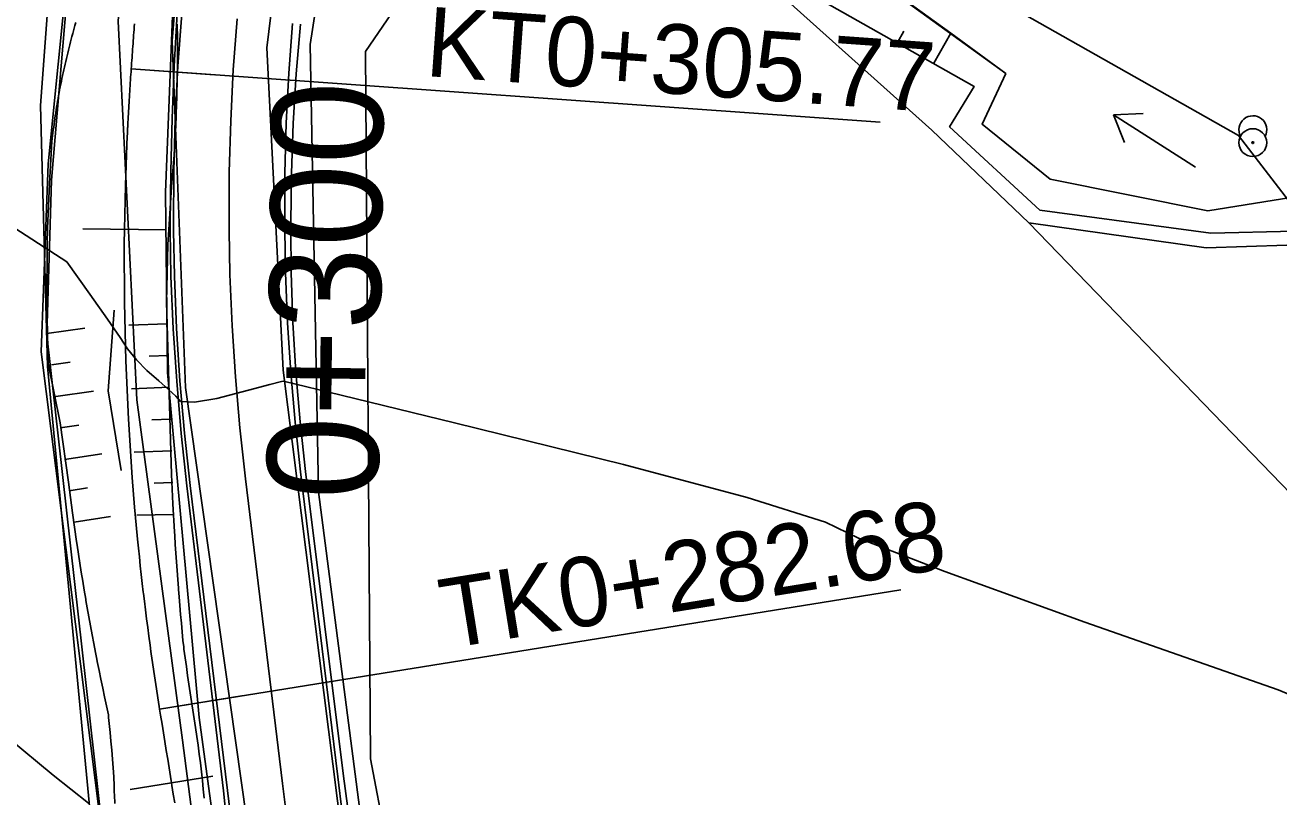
# Model space of a CAD drawing. Extents: x -574342 to -508101, y -1143544 to -1123894.
# Drawn here: x -508550.57 to -508505.49, y -1143220.32 to -1143192.58 of the extents above; entities that cross this region are included whole.
import ezdxf

# ---------------------------------------------------------------- set-up
doc = ezdxf.new("R2010")
doc.units = 0
for name, color, linetype in [('01_PARCELY_NAVRH_PC', 7, 'Continuous'), ('01_PARCELY_NAVRH_VHO', 7, 'Continuous'), ('01_PARCELY_NAVRH_ŽP', 7, 'Continuous'), ('05_VHO_V_TOK_STAV', 7, 'Continuous'), ('1000', 7, 'Continuous'), ('18', 7, 'Continuous'), ('21', 7, 'Continuous'), ('23', 7, 'Continuous'), ('30', 7, 'Continuous'), ('37', 7, 'Continuous'), ('42', 7, 'Continuous'), ('43', 7, 'Continuous'), ('55', 7, 'Continuous'), ('6', 7, 'Continuous'), ('60', 7, 'Continuous'), ('61', 7, 'Continuous'), ('62', 7, 'Continuous'), ('tab', 7, 'Continuous'), ('VRST VEDL', 7, 'Continuous')]:
    doc.layers.add(name, color=color, linetype=linetype)

msp = doc.modelspace()

# ---------------------------------------------------------------- linework, layer by layer
for p, q in [((-508549.793, -1143203.663), (-508548.424, -1143203.467)), ((-508545.467, -1143203.314), (-508546.849, -1143203.364)), ((-508546.114, -1143204.481), (-508545.428, -1143204.456)), ((-508548.95, -1143204.696), (-508549.63, -1143204.793)), ((-508549.471, -1143205.925), (-508548.117, -1143205.737)), ((-508545.385, -1143205.598), (-508546.751, -1143205.652)), ((-508546.02, -1143206.767), (-508545.338, -1143206.739)), ((-508548.639, -1143206.964), (-508549.316, -1143207.056)), ((-508549.16, -1143208.188), (-508547.81, -1143207.995)), ((-508545.292, -1143207.881), (-508546.654, -1143207.929)), ((-508545.932, -1143209.04), (-508545.258, -1143209.023)), ((-508548.325, -1143209.216), (-508548.992, -1143209.318)), ((-508548.815, -1143210.447), (-508547.506, -1143210.242)), ((-508545.233, -1143210.165), (-508546.557, -1143210.194))]:
    msp.add_line(p, q)
at = {"layer": '01_PARCELY_NAVRH_PC'}
msp.add_lwpolyline([(-508524.26, -1143263.08), (-508531.16, -1143250.06), (-508535.34, -1143238.37), (-508537.02, -1143231.11), (-508538.46, -1143221.35), (-508540.02, -1143209.35), (-508540.32, -1143193.28), (-508538.65, -1143182.46), (-508537.18, -1143176.51), (-508541.94, -1143173.53), (-508544.25, -1143181.83), (-508544.97, -1143188.3), (-508545.24, -1143191.32), (-508545.52, -1143198.58), (-508545.45, -1143205.07), (-508544.32, -1143217.47), (-508542.83, -1143228.38), (-508540.55, -1143238.43), (-508539.77, -1143241.25), (-508539.07, -1143243.44), (-508536.24, -1143250.83), (-508534.5, -1143254.93), (-508531.94, -1143260.32)], dxfattribs=at)
msp.add_lwpolyline([(-508524.26, -1143263.08), (-508531.16, -1143250.06), (-508535.34, -1143238.37), (-508537.02, -1143231.11), (-508538.46, -1143221.35), (-508540.02, -1143209.35), (-508540.32, -1143193.28), (-508538.65, -1143182.46), (-508537.18, -1143176.51), (-508541.94, -1143173.53), (-508544.25, -1143181.83), (-508544.97, -1143188.3), (-508545.24, -1143191.32), (-508545.52, -1143198.58), (-508545.45, -1143205.07), (-508544.32, -1143217.47), (-508542.83, -1143228.38), (-508540.55, -1143238.43), (-508539.77, -1143241.25), (-508539.07, -1143243.44), (-508536.24, -1143250.83), (-508534.5, -1143254.93), (-508531.94, -1143260.32)], dxfattribs=at)
at = {"layer": '01_PARCELY_NAVRH_VHO'}
msp.add_lwpolyline([(-508551.68, -1143170.14), (-508549.4, -1143169.86), (-508545.04, -1143171.57), (-508537.18, -1143176.51), (-508534.6, -1143178.15), (-508533.13, -1143181.54), (-508526.17, -1143187.6), (-508523.49, -1143191.39), (-508517.97, -1143196.35), (-508514.48, -1143199.68), (-508508.1, -1143200.58), (-508505.21, -1143200.49), (-508503.8, -1143201.12), (-508497.27, -1143211.29), (-508498.42, -1143216.3), (-508497.14, -1143220.02), (-508490.67, -1143220.8), (-508485.31, -1143225.73), (-508480.78, -1143231.64), (-508476.67, -1143241.6), (-508474.42, -1143249.95), (-508480.76, -1143258.08), (-508469.74, -1143257.73), (-508446.21, -1143255.76)], dxfattribs=at)
for points in [[(-508536.24, -1143250.83), (-508539.07, -1143243.44), (-508539.77, -1143241.25), (-508540.55, -1143238.43), (-508542.83, -1143228.38), (-508544.32, -1143217.47), (-508545.45, -1143205.07), (-508545.52, -1143198.58), (-508545.24, -1143191.32), (-508544.97, -1143188.3), (-508544.25, -1143181.83), (-508551.68, -1143170.14), (-508558.5, -1143170.32), (-508555.03, -1143173.64), (-508548.66, -1143186.8), (-508549.748, -1143197.559), (-508549.999, -1143204.321), (-508547.53, -1143223.9), (-508542.99, -1143242.68), (-508538.24, -1143253.15)], [(-508536.24, -1143250.83), (-508539.07, -1143243.44), (-508539.77, -1143241.25), (-508540.55, -1143238.43), (-508542.83, -1143228.38), (-508544.32, -1143217.47), (-508545.45, -1143205.07), (-508545.52, -1143198.58), (-508545.24, -1143191.32), (-508544.97, -1143188.3), (-508544.25, -1143181.83), (-508551.68, -1143170.14), (-508558.5, -1143170.32), (-508555.03, -1143173.64), (-508548.66, -1143186.8), (-508549.63, -1143198.15), (-508549.79, -1143203.71), (-508547.53, -1143223.9), (-508542.99, -1143242.68), (-508538.24, -1143253.15)]]:
    msp.add_lwpolyline(points, close=True, dxfattribs=at)
at = {"layer": '01_PARCELY_NAVRH_ŽP'}
for points in [[(-508555.03, -1143173.64), (-508548.66, -1143186.8), (-508549.63, -1143198.15), (-508549.79, -1143203.71), (-508547.53, -1143223.9), (-508542.99, -1143242.68), (-508538.24, -1143253.15), (-508539.95, -1143255.3), (-508547.25, -1143258.62), (-508651.11, -1143191.46), (-508662.59, -1143152.85), (-508637.59, -1143153.08), (-508621.09, -1143158.13), (-508610.87, -1143164.96), (-508585.59, -1143176.01), (-508569.25, -1143175.97)], [(-508498.42, -1143216.3), (-508514.48, -1143199.68), (-508508.1, -1143200.58), (-508505.21, -1143200.49), (-508503.8, -1143201.12), (-508497.27, -1143211.29)]]:
    msp.add_lwpolyline(points, close=True, dxfattribs=at)
at = {"layer": '05_VHO_V_TOK_STAV'}
msp.add_lwpolyline([(-508447.49, -1143245.57), (-508453.89, -1143245.84), (-508469.84, -1143247.46), (-508476.067, -1143236.175), (-508482.77, -1143224.26), (-508489.11, -1143218.88), (-508496.94, -1143217.04), (-508494.75, -1143210.95), (-508502.24, -1143200.02), (-508504.69, -1143198.72), (-508508.04, -1143199.26), (-508513.72, -1143198.12), (-508516.16, -1143196.14), (-508515.31, -1143194.32), (-508517.287, -1143192.866), (-508519.733, -1143191.098), (-508522.24, -1143189.31), (-508524.27, -1143185.62), (-508530.674, -1143178.031), (-508542.01, -1143169.37), (-508547.92, -1143166.82), (-508560.33, -1143168.91)], dxfattribs=at)
at = {"layer": '1000'}
for points in [[(-508545.104, -1143192.163), (-508545.213, -1143194.05), (-508545.284, -1143195.939), (-508545.338, -1143197.827), (-508545.358, -1143199.717), (-508545.357, -1143199.972), (-508545.333, -1143201.606), (-508545.255, -1143203.494), (-508545.115, -1143205.379), (-508544.96, -1143207.262), (-508544.763, -1143209.141), (-508543.435, -1143220.105), (-508543.18, -1143222.696)], [(-508544.942, -1143192.177), (-508545.082, -1143194.059), (-508545.178, -1143195.943), (-508545.231, -1143197.829), (-508545.24, -1143199.716), (-508545.238, -1143199.971), (-508545.206, -1143201.603), (-508545.129, -1143203.488), (-508545.009, -1143205.371), (-508544.845, -1143207.251), (-508544.637, -1143209.126), (-508543.299, -1143220.089), (-508542.983, -1143222.672)], [(-508547.349, -1143220.564), (-508547.362, -1143220.243), (-508547.365, -1143220.151), (-508547.375, -1143219.922), (-508547.388, -1143219.601), (-508547.402, -1143219.28), (-508547.428, -1143218.961), (-508547.457, -1143218.642), (-508547.487, -1143218.324), (-508547.517, -1143218.005), (-508547.548, -1143217.687), (-508547.569, -1143217.466), (-508547.579, -1143217.367), (-508547.649, -1143217.049), (-508547.717, -1143216.731), (-508547.784, -1143216.412), (-508547.85, -1143216.093), (-508547.915, -1143215.774), (-508547.979, -1143215.454), (-508547.996, -1143215.367), (-508548.041, -1143215.134), (-508548.103, -1143214.814), (-508548.163, -1143214.494), (-508548.222, -1143214.173), (-508548.281, -1143213.852), (-508548.338, -1143213.531), (-508548.385, -1143213.258), (-508548.394, -1143213.21), (-508548.449, -1143212.888), (-508548.502, -1143212.566), (-508548.555, -1143212.244), (-508548.606, -1143211.922), (-508548.657, -1143211.599), (-508548.706, -1143211.276), (-508548.727, -1143211.138), (-508548.874, -1143210.105), (-508549.014, -1143209.009), (-508549.311, -1143206.875), (-508549.744, -1143204.738), (-508549.796, -1143202.581), (-508549.781, -1143200.423), (-508549.767, -1143199.884), (-508549.701, -1143198.268), (-508549.607, -1143196.763), (-508549.597, -1143196.659), (-508549.585, -1143196.556), (-508549.572, -1143196.452), (-508549.56, -1143196.349), (-508549.546, -1143196.245), (-508549.533, -1143196.142), (-508549.529, -1143196.117), (-508549.519, -1143196.039), (-508549.504, -1143195.935), (-508549.489, -1143195.832), (-508549.473, -1143195.729), (-508549.457, -1143195.626), (-508549.441, -1143195.522), (-508549.424, -1143195.419), (-508549.406, -1143195.316), (-508549.388, -1143195.213), (-508549.37, -1143195.11), (-508549.351, -1143195.007), (-508549.332, -1143194.905), (-508549.312, -1143194.802), (-508549.291, -1143194.699), (-508549.27, -1143194.596), (-508549.249, -1143194.494), (-508549.227, -1143194.391), (-508549.204, -1143194.289), (-508549.181, -1143194.186), (-508549.158, -1143194.084), (-508549.135, -1143193.985), (-508549.134, -1143193.982), (-508549.111, -1143193.882), (-508549.088, -1143193.782), (-508549.064, -1143193.682), (-508549.04, -1143193.583), (-508549.016, -1143193.483), (-508548.991, -1143193.383), (-508548.966, -1143193.283), (-508548.941, -1143193.183), (-508548.915, -1143193.084), (-508548.889, -1143192.984), (-508548.863, -1143192.884), (-508548.837, -1143192.785), (-508548.81, -1143192.685), (-508548.783, -1143192.586), (-508548.755, -1143192.486)], [(-508544.13, -1143220.369), (-508544.165, -1143220.051), (-508544.2, -1143219.733), (-508544.21, -1143219.642), (-508544.235, -1143219.416), (-508544.271, -1143219.098), (-508544.313, -1143218.782), (-508544.354, -1143218.465), (-508544.4, -1143218.149), (-508544.448, -1143217.834), (-508544.496, -1143217.518), (-508544.544, -1143217.203), (-508544.577, -1143216.983), (-508544.592, -1143216.889), (-508544.64, -1143216.577), (-508544.686, -1143216.265), (-508544.731, -1143215.953), (-508544.775, -1143215.64), (-508544.818, -1143215.328), (-508544.86, -1143215.015), (-508544.871, -1143214.93), (-508544.896, -1143214.702), (-508544.926, -1143214.388), (-508544.955, -1143214.074), (-508544.983, -1143213.76), (-508545.011, -1143213.445), (-508545.037, -1143213.131), (-508545.058, -1143212.864), (-508545.062, -1143212.817), (-508545.086, -1143212.503), (-508545.11, -1143212.188), (-508545.132, -1143211.874), (-508545.153, -1143211.559), (-508545.174, -1143211.245), (-508545.193, -1143210.93), (-508545.201, -1143210.796), (-508545.256, -1143209.791), (-508545.304, -1143208.727), (-508545.371, -1143206.658), (-508545.435, -1143204.592), (-508545.487, -1143202.525), (-508545.438, -1143200.459), (-508545.411, -1143199.943), (-508545.311, -1143198.395), (-508545.194, -1143196.956), (-508545.186, -1143196.857), (-508545.178, -1143196.758), (-508545.173, -1143196.658), (-508545.169, -1143196.559), (-508545.165, -1143196.46), (-508545.161, -1143196.36), (-508545.16, -1143196.336), (-508545.157, -1143196.261), (-508545.153, -1143196.161), (-508545.149, -1143196.062), (-508545.146, -1143195.962), (-508545.142, -1143195.863), (-508545.139, -1143195.763), (-508545.136, -1143195.664), (-508545.132, -1143195.564), (-508545.129, -1143195.465), (-508545.126, -1143195.365), (-508545.123, -1143195.266), (-508545.121, -1143195.166), (-508545.118, -1143195.066), (-508545.115, -1143194.967), (-508545.113, -1143194.867), (-508545.111, -1143194.768), (-508545.108, -1143194.668), (-508545.106, -1143194.568), (-508545.104, -1143194.469), (-508545.102, -1143194.369), (-508545.1, -1143194.273), (-508545.1, -1143194.269), (-508545.099, -1143194.168), (-508545.098, -1143194.066), (-508545.097, -1143193.965), (-508545.096, -1143193.863), (-508545.095, -1143193.762), (-508545.095, -1143193.66), (-508545.095, -1143193.559), (-508545.095, -1143193.457), (-508545.095, -1143193.356), (-508545.095, -1143193.254), (-508545.096, -1143193.153), (-508545.096, -1143193.051), (-508545.097, -1143192.95), (-508545.099, -1143192.848), (-508545.1, -1143192.746), (-508545.103, -1143192.645), (-508545.106, -1143192.543)], [(-508540.957, -1143192.519), (-508541.09, -1143194.309), (-508541.181, -1143196.101), (-508541.231, -1143197.895), (-508541.24, -1143199.69), (-508541.239, -1143199.932), (-508541.208, -1143201.485), (-508541.135, -1143203.278), (-508541.02, -1143205.069), (-508540.864, -1143206.857), (-508540.667, -1143208.641), (-508539.328, -1143219.604), (-508539.013, -1143222.188)], [(-508540.675, -1143192.543), (-508540.829, -1143194.325), (-508540.935, -1143196.111), (-508540.999, -1143197.899), (-508541.022, -1143199.689), (-508541.022, -1143199.93), (-508541.003, -1143201.479), (-508540.942, -1143203.268), (-508540.833, -1143205.055), (-508540.68, -1143206.839), (-508540.485, -1143208.619), (-508539.124, -1143219.579), (-508538.777, -1143222.159)]]:
    msp.add_lwpolyline(points, dxfattribs=at)
at = {"layer": '21'}
for points in [[(-508542.949, -1143192.348), (-508543.086, -1143194.184), (-508543.18, -1143196.022), (-508543.231, -1143197.862), (-508543.24, -1143199.703), (-508543.238, -1143199.951), (-508543.207, -1143201.544), (-508543.132, -1143203.383), (-508543.014, -1143205.22), (-508542.854, -1143207.054), (-508542.652, -1143208.884), (-508541.313, -1143219.846), (-508540.998, -1143222.43)], [(-508545.193, -1143220.54), (-508545.244, -1143220.225), (-508545.295, -1143219.91), (-508545.309, -1143219.819), (-508545.346, -1143219.595), (-508545.396, -1143219.28), (-508545.447, -1143218.965), (-508545.498, -1143218.65), (-508545.549, -1143218.335), (-508545.599, -1143218.02), (-508545.65, -1143217.704), (-508545.701, -1143217.389), (-508545.736, -1143217.17), (-508545.752, -1143217.074), (-508545.802, -1143216.759), (-508545.851, -1143216.444), (-508545.899, -1143216.128), (-508545.946, -1143215.813), (-508545.992, -1143215.497), (-508546.036, -1143215.181), (-508546.049, -1143215.095), (-508546.08, -1143214.865), (-508546.123, -1143214.549), (-508546.165, -1143214.232), (-508546.206, -1143213.916), (-508546.246, -1143213.599), (-508546.285, -1143213.282), (-508546.317, -1143213.013), (-508546.323, -1143212.966), (-508546.36, -1143212.649), (-508546.395, -1143212.331), (-508546.43, -1143212.014), (-508546.464, -1143211.697), (-508546.497, -1143211.379), (-508546.529, -1143211.062), (-508546.542, -1143210.926), (-508546.635, -1143209.911), (-508546.723, -1143208.835), (-508546.86, -1143206.74), (-508546.953, -1143204.643), (-508547.002, -1143202.545), (-508547.007, -1143200.446), (-508547.002, -1143199.921), (-508546.968, -1143198.347), (-508546.915, -1143196.881), (-508546.91, -1143196.78), (-508546.906, -1143196.679), (-508546.901, -1143196.577), (-508546.896, -1143196.476), (-508546.891, -1143196.375), (-508546.886, -1143196.274), (-508546.885, -1143196.25), (-508546.881, -1143196.173), (-508546.876, -1143196.072), (-508546.871, -1143195.971), (-508546.865, -1143195.869), (-508546.86, -1143195.768), (-508546.854, -1143195.667), (-508546.848, -1143195.566), (-508546.843, -1143195.465), (-508546.837, -1143195.364), (-508546.831, -1143195.263), (-508546.825, -1143195.162), (-508546.818, -1143195.061), (-508546.812, -1143194.96), (-508546.806, -1143194.858), (-508546.799, -1143194.757), (-508546.792, -1143194.656), (-508546.786, -1143194.555), (-508546.779, -1143194.454), (-508546.772, -1143194.353), (-508546.765, -1143194.252), (-508546.758, -1143194.155), (-508546.758, -1143194.151), (-508546.751, -1143194.05), (-508546.743, -1143193.949), (-508546.736, -1143193.848), (-508546.729, -1143193.747), (-508546.722, -1143193.646), (-508546.715, -1143193.545), (-508546.707, -1143193.444), (-508546.7, -1143193.343), (-508546.693, -1143193.242), (-508546.686, -1143193.141), (-508546.679, -1143193.04), (-508546.671, -1143192.939), (-508546.664, -1143192.838), (-508546.657, -1143192.737), (-508546.65, -1143192.636), (-508546.643, -1143192.535)]]:
    msp.add_lwpolyline(points, dxfattribs=at)
at = {"layer": '23'}
for points in [[(-508546.758, -1143194.155), (-508519.826, -1143196.072)], [(-508546.758, -1143194.155), (-508543.766, -1143194.368)], [(-508545.736, -1143217.17), (-508519.08, -1143212.874)], [(-508545.736, -1143217.17), (-508542.775, -1143216.693)]]:
    msp.add_lwpolyline(points, dxfattribs=at)
at = {"layer": '30'}
for radius in [0.5, 0.0327]:
    msp.add_circle((-508506.427, -1143196.801), radius, dxfattribs=at)
msp.add_arc((-508506.427, -1143196.338), 0.5, 331.7891, 208.7844, dxfattribs=at)
at = {"layer": '37'}
for points in [[(-508453.89, -1143245.84), (-508462.52, -1143247.11), (-508469.84, -1143247.46), (-508479.32, -1143230.73), (-508482.77, -1143224.26), (-508489.11, -1143218.88), (-508496.94, -1143217.04), (-508494.75, -1143210.95), (-508502.24, -1143200.02), (-508504.69, -1143198.72), (-508508.04, -1143199.26), (-508513.72, -1143198.12), (-508516.16, -1143196.14), (-508515.31, -1143194.32), (-508522.24, -1143189.31), (-508524.27, -1143185.62), (-508530.09, -1143178.84), (-508531.6, -1143177.56), (-508524.5, -1143179.18), (-508517.75, -1143180.38), (-508509.75, -1143181.27)], [(-508453.89, -1143245.84), (-508462.52, -1143247.11), (-508469.84, -1143247.46), (-508479.32, -1143230.73), (-508482.77, -1143224.26), (-508489.11, -1143218.88), (-508496.94, -1143217.04), (-508494.75, -1143210.95), (-508502.24, -1143200.02), (-508504.69, -1143198.72), (-508508.04, -1143199.26), (-508513.72, -1143198.12), (-508516.16, -1143196.14), (-508515.31, -1143194.32), (-508522.24, -1143189.31), (-508524.27, -1143185.62), (-508530.09, -1143178.84), (-508531.6, -1143177.56), (-508524.5, -1143179.18), (-508517.75, -1143180.38), (-508509.75, -1143181.27)], [(-508544.44, -1143182.59), (-508545.29, -1143193.14), (-508544.8, -1143205.6), (-508541.6, -1143228.19), (-508538.07, -1143243), (-508531.89, -1143258.66), (-508522.3, -1143275.29), (-508518.1, -1143283.75), (-508512.73, -1143299.25), (-508510.49, -1143313.12)], [(-508544.44, -1143182.59), (-508545.29, -1143193.14), (-508544.8, -1143205.6), (-508541.6, -1143228.19), (-508538.07, -1143243), (-508531.89, -1143258.66), (-508522.3, -1143275.29), (-508518.1, -1143283.75), (-508512.73, -1143299.25), (-508510.49, -1143313.12)], [(-508507.09, -1143312.37), (-508509.64, -1143298.16), (-508515.1, -1143282.44), (-508519.8, -1143273.76), (-508526.92, -1143261.04), (-508530.09, -1143253.58), (-508534.91, -1143241.83), (-508538.52, -1143226.92), (-508541.3, -1143204.98), (-508541.88, -1143193.39), (-508540.68, -1143183.59)], [(-508507.09, -1143312.37), (-508509.64, -1143298.16), (-508515.1, -1143282.44), (-508519.8, -1143273.76), (-508526.92, -1143261.04), (-508530.09, -1143253.58), (-508534.91, -1143241.83), (-508538.52, -1143226.92), (-508541.3, -1143204.98), (-508541.88, -1143193.39), (-508540.68, -1143183.59)]]:
    msp.add_lwpolyline(points, dxfattribs=at)
at = {"layer": '42'}
for points in [[(-508538.33, -1143193.52), (-508529.17, -1143180.12), (-508522.42, -1143187.78), (-508506.94, -1143196.54), (-508494.29, -1143213), (-508482.23, -1143223.86), (-508469.17, -1143251.83), (-508475.71, -1143257.35)], [(-508538.33, -1143193.52), (-508529.17, -1143180.12), (-508522.42, -1143187.78), (-508506.94, -1143196.54), (-508494.29, -1143213), (-508482.23, -1143223.86), (-508469.17, -1143251.83), (-508475.71, -1143257.35)], [(-508475.71, -1143257.35), (-508496.39, -1143258.35), (-508520.72, -1143253.86), (-508528.66, -1143251.18), (-508534.38, -1143238.75), (-508538.15, -1143218.95), (-508538.33, -1143193.52)], [(-508475.71, -1143257.35), (-508496.39, -1143258.35), (-508520.72, -1143253.86), (-508528.66, -1143251.18), (-508534.38, -1143238.75), (-508538.15, -1143218.95), (-508538.33, -1143193.52)]]:
    msp.add_lwpolyline(points, dxfattribs=at)
at = {"layer": '43'}
for p, q in [((-508511.435, -1143195.807), (-508510.368, -1143195.751)), ((-508508.483, -1143197.689), (-508511.435, -1143195.807)), ((-508511.036, -1143196.798), (-508511.435, -1143195.807))]:
    msp.add_line(p, q, dxfattribs=at)
at = {"layer": '55'}
for points in [[(-508550.02, -1143195.47), (-508549.4, -1143187.04), (-508552.57, -1143188.07)], [(-508550.02, -1143195.47), (-508549.4, -1143187.04), (-508552.57, -1143188.07)], [(-508550.02, -1143195.47), (-508549.77, -1143204.85), (-508547.83, -1143225.16)], [(-508550.02, -1143195.47), (-508549.77, -1143204.85), (-508547.83, -1143225.16)]]:
    msp.add_lwpolyline(points, dxfattribs=at)
at = {"layer": '6'}
for points in [[(-508548.501, -1143199.901), (-508545.502, -1143199.941)], [(-508547.002, -1143199.921), (-508547.002, -1143199.921)], [(-508546.79, -1143220.058), (-508543.828, -1143219.581)]]:
    msp.add_lwpolyline(points, dxfattribs=at)
at = {"layer": '60'}
msp.add_lwpolyline([(-508525.16, -1143176.55), (-508530.6, -1143175.07), (-508532.55, -1143176.28), (-508533.83, -1143178.28), (-508532.4, -1143181.41), (-508525.65, -1143187.42), (-508523.14, -1143191), (-508516.45, -1143194.78), (-508517.33, -1143196.24), (-508514.08, -1143199.23), (-508507.94, -1143200.06), (-508504.93, -1143199.98), (-508503.26, -1143200.81), (-508496.6, -1143211.46), (-508497.83, -1143216.41), (-508496.7, -1143219.56), (-508489.97, -1143220.34), (-508484.25, -1143225.74), (-508480.17, -1143231.74), (-508475.87, -1143242.05), (-508473.98, -1143249.93), (-508471.29, -1143252.95)], dxfattribs=at)
msp.add_lwpolyline([(-508525.16, -1143176.55), (-508530.6, -1143175.07), (-508532.55, -1143176.28), (-508533.83, -1143178.28), (-508532.4, -1143181.41), (-508525.65, -1143187.42), (-508523.14, -1143191), (-508516.45, -1143194.78), (-508517.33, -1143196.24), (-508514.08, -1143199.23), (-508507.94, -1143200.06), (-508504.93, -1143199.98), (-508503.26, -1143200.81), (-508496.6, -1143211.46), (-508497.83, -1143216.41), (-508496.7, -1143219.56), (-508489.97, -1143220.34), (-508484.25, -1143225.74), (-508480.17, -1143231.74), (-508475.87, -1143242.05), (-508473.98, -1143249.93), (-508471.29, -1143252.95)], dxfattribs=at)
at = {"layer": '61'}
for p, q in [((-508519.205, -1143193.208), (-508518.973, -1143192.8)), ((-508519.205, -1143193.208), (-508518.973, -1143192.8)), ((-508517.9, -1143193.947), (-508517.287, -1143192.866)), ((-508517.9, -1143193.947), (-508517.287, -1143192.866))]:
    msp.add_line(p, q, dxfattribs=at)
at = {"layer": '62'}
msp.add_lwpolyline([(-508535.82, -1143252.17), (-508543.49, -1143229.3), (-508544.91, -1143218.28), (-508546.55, -1143206.05), (-508547.23, -1143192.43), (-508546.71, -1143185.69)], dxfattribs=at)
msp.add_lwpolyline([(-508535.82, -1143252.17), (-508543.49, -1143229.3), (-508544.91, -1143218.28), (-508546.55, -1143206.05), (-508547.23, -1143192.43), (-508546.71, -1143185.69)], dxfattribs=at)
at = {"layer": 'tab'}
msp.add_lwpolyline([(-508547.12, -1143208.584), (-508547.582, -1143205.722), (-508547.376, -1143202.83)], dxfattribs=at)
at = {"layer": 'VRST VEDL'}
for points in [[(-508551.349, -1143199.615), (-508549.073, -1143201.087), (-508548.245, -1143202.246), (-508547.605, -1143203.153), (-508547.152, -1143203.809), (-508546.887, -1143204.213), (-508546.567, -1143204.606), (-508546.192, -1143204.99), (-508545.762, -1143205.363), (-508545.417, -1143205.674), (-508545.157, -1143205.922), (-508544.982, -1143206.108), (-508544.488, -1143206.133), (-508543.676, -1143205.997), (-508542.546, -1143205.702), (-508541.77, -1143205.5), (-508541.348, -1143205.394), (-508541.28, -1143205.382), (-508539.209, -1143205.875), (-508535.135, -1143206.871), (-508529.057, -1143208.372), (-508524.61, -1143209.564), (-508521.793, -1143210.448), (-508520.605, -1143211.024), (-508517.497, -1143212.221), (-508512.469, -1143214.039), (-508505.52, -1143216.478), (-508500.057, -1143218.745)], [(-508551.177, -1143218.195), (-508549.563, -1143219.538), (-508548.295, -1143220.549)]]:
    msp.add_lwpolyline(points, dxfattribs=at)

# ---------------------------------------------------------------- texts
at = {"layer": '18'}
for s, height, rotation, p in [('KT0+305.77', 2.5, 355.927, (-508536.217, -1143194.404)), ('0+300', 4, 89.2346, (-508537.885, -1143209.651)), ('TK0+282.68', 2.5, 9.1564, (-508535.422, -1143215.001))]:
    msp.add_text(s, height=height, rotation=rotation, dxfattribs=at).set_placement(p)

doc.saveas('drawing.dxf')
